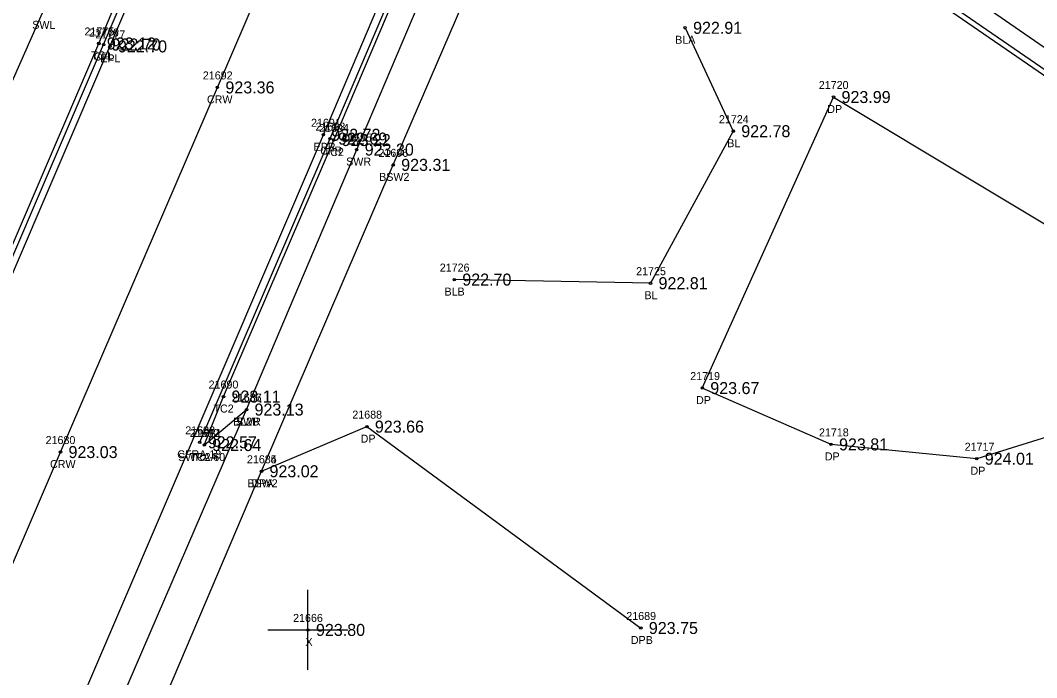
# Model space of a CAD drawing. Extents: x 1576181 to 1577685, y 1099396 to 1101490.
# Drawn here: x 1577167.3 to 1577294.3, y 1100920.8 to 1101003 of the extents above; entities that cross this region are included whole.
import ezdxf

# ---------------------------------------------------------------- set-up
doc = ezdxf.new("R2010")
doc.units = 0
for name, color, linetype in [('RD_DTM_BkLn1', 7, 'Continuous'), ('RD_DTM_BkLn2', 7, 'Continuous'), ('RD_DTM_BkLn_txCode', 7, 'Continuous'), ('RD_EX_Conc', 7, 'Continuous'), ('RD_EX_Conc_txCode', 7, 'Continuous'), ('RD_EX_Driveway', 7, 'Continuous'), ('RD_EX_Driveway_txCode', 7, 'Continuous'), ('RD_EX_Misc', 7, 'Continuous'), ('RD_EX_Misc_txCode', 7, 'Continuous'), ('RD_EX_Road', 7, 'Continuous'), ('RD_EX_Road_txCode', 7, 'Continuous'), ('RD_EX_TX_Conc_ELEV', 7, 'Continuous'), ('RD_EX_TX_Driveway_ELEV', 7, 'Continuous'), ('RD_EX_TX_Misc_ELEV', 7, 'Continuous'), ('RD_EX_TX_Road_ELEV', 7, 'Continuous'), ('RD_HC_Survey_ELEV', 7, 'Continuous'), ('RD_HC_Survey_txCode', 7, 'Continuous'), ('RD_SMD_Locator', 7, 'Continuous')]:
    doc.layers.add(name, color=color, linetype=linetype)

msp = doc.modelspace()

# ---------------------------------------------------------------- linework, layer by layer
at = {"layer": 'RD_DTM_BkLn1'}
msp.add_line((1577174.89, 1100906.42), (1577195.57, 1100954.33), dxfattribs=at)
for points in [[(1576908.25, 1100441.74), (1576920.44, 1100463.64), (1576944.47, 1100507.42), (1576973.89, 1100560.12), (1576993.13, 1100594.33), (1577014.77, 1100632.79), (1577042.14, 1100681.68), (1577066.82, 1100725.12), (1577089.75, 1100766.04), (1577111.87, 1100810.02), (1577132.74, 1100857.48), (1577152.58, 1100903.02), (1577172.32, 1100949.02), (1577191.93, 1100994.6), (1577211.77, 1101040.76), (1577222.24, 1101065.99), (1577231.17, 1101086.4), (1577251.41, 1101132.37), (1577271.56, 1101178.18), (1577291.61, 1101224.24), (1577311.77, 1101270.05), (1577333.79, 1101320.46), (1577355.93, 1101371.29), (1577365.01, 1101392.03)], [(1577250.38, 1101002.05), (1577256.4, 1100989.13), (1577246.06, 1100970.13), (1577221.54, 1100970.58)]]:
    msp.add_lwpolyline(points, dxfattribs=at)
at = {"layer": 'RD_DTM_BkLn2'}
for points in [[(1577190.28, 1100949.9), (1577192.69, 1100955.96), (1577206.46, 1100988.02), (1577223.59, 1101028.27), (1577225.54, 1101030.74), (1577227.54, 1101032.05), (1577227.96, 1101031.82), (1577225.99, 1101027.04)], [(1577107.29, 1100837.15), (1577118.47, 1100863.11), (1577138.23, 1100909.32), (1577157.86, 1100955.31), (1577177.11, 1101000.09), (1577190, 1101030.75)], [(1577246.74, 1101029.36), (1577254.79, 1101023.97), (1577296.49, 1100995.27), (1577317.47, 1100980.16)]]:
    msp.add_lwpolyline(points, dxfattribs=at)
at = {"layer": 'RD_EX_Conc'}
for points in [[(1577079.25, 1100805.08), (1577097.11, 1100838.84), (1577109.69, 1100867.34), (1577130.74, 1100915.04), (1577150.18, 1100959), (1577170.08, 1101003.92), (1577196.78, 1101064.66), (1577202.49, 1101060)], [(1577189.73, 1100950.24), (1577206.01, 1100988.2), (1577223.14, 1101028.48), (1577225.21, 1101031.19), (1577227.4, 1101032.52), (1577228.46, 1101031.9), (1577226.35, 1101026.9)], [(1577107.98, 1100836.94), (1577119.09, 1100862.85), (1577138.71, 1100909.15), (1577158.46, 1100955.15), (1577177.7, 1100999.96), (1577190.71, 1101030.46)], [(1577247, 1101029.77), (1577255.15, 1101024.5), (1577296.85, 1100995.79), (1577317.96, 1100980.41)], [(1577190.28, 1100949.9), (1577195.57, 1100954.33), (1577209.34, 1100986.83), (1577226.35, 1101026.9)], [(1577055.15, 1100662.64), (1577085.17, 1100716.01), (1577085.17, 1100716.01), (1577107.37, 1100755.87), (1577118.9, 1100776.66), (1577132.78, 1100800.81), (1577154.83, 1100846.62), (1577163.04, 1100865.24), (1577174.66, 1100893.05), (1577197.44, 1100946.62), (1577213.9, 1100984.92), (1577231.04, 1101024.71)]]:
    msp.add_lwpolyline(points, dxfattribs=at)
at = {"layer": 'RD_EX_Driveway'}
for points in [[(1577332.84, 1100969.65), (1577326.58, 1100968.01), (1577315.89, 1100957.23), (1577286.83, 1100948.19), (1577268.62, 1100949.98), (1577252.53, 1100957.02), (1577268.93, 1100993.4), (1577305.23, 1100971.57), (1577315.9, 1100975.76), (1577317.96, 1100980.41), (1577332.84, 1100969.65)], [(1577197.44, 1100946.62), (1577210.61, 1100952.2), (1577244.85, 1100927.03)]]:
    msp.add_lwpolyline(points, dxfattribs=at)
at = {"layer": 'RD_EX_Misc'}
for p, q in [((1577203.25, 1100921.79), (1577203.25, 1100931.79)), ((1577198.25, 1100926.79), (1577208.25, 1100926.79))]:
    msp.add_line(p, q, dxfattribs=at)
at = {"layer": 'RD_EX_Road'}
for points in [[(1577060.61, 1100805.43), (1577075.53, 1100798.54), (1577081.93, 1100797.67), (1577087.92, 1100798.37), (1577091.21, 1100799.4), (1577094.49, 1100804.27), (1577106.9, 1100832.16), (1577119.9, 1100862.62), (1577139.86, 1100909.4), (1577159.21, 1100954.77), (1577178.5, 1100999.73), (1577192.43, 1101032.31), (1577206.43, 1101064.72)], [(1577078.76, 1100718.33), (1577101.64, 1100758.92), (1577113.34, 1100780.09), (1577125.29, 1100804.69), (1577146.47, 1100851.25), (1577166.06, 1100897.32), (1577205.17, 1100988.68), (1577222.29, 1101028.96), (1577224.55, 1101032.02), (1577228.3, 1101034.47), (1577233.18, 1101036.1), (1577233.18, 1101036.1), (1577237.42, 1101035.84), (1577245.43, 1101032.85), (1577248.28, 1101031.55), (1577256.85, 1101026.16), (1577298.2, 1100997.6), (1577319.21, 1100982.29), (1577334.07, 1100971.38), (1577345.18, 1100963.67), (1577378, 1100938.95), (1577407.15, 1100918.71), (1577419.5, 1100910.06), (1577460.72, 1100880.37)]]:
    msp.add_lwpolyline(points, dxfattribs=at)
at = {"layer": 'RD_SMD_Locator'}
for centre in [(1577250.38, 1101002.05), (1577177.11, 1101000.09), (1577177.7, 1100999.96), (1577178.5, 1100999.73), (1577191.93, 1100994.6), (1577268.93, 1100993.4), (1577256.4, 1100989.13), (1577205.17, 1100988.68), (1577206.01, 1100988.2), (1577206.46, 1100988.02), (1577209.34, 1100986.83), (1577213.9, 1100984.92), (1577221.54, 1100970.58), (1577246.06, 1100970.13), (1577252.53, 1100957.02), (1577192.69, 1100955.96), (1577195.57, 1100954.33), (1577195.57, 1100954.33), (1577210.61, 1100952.2), (1577189.73, 1100950.24), (1577190.28, 1100949.9), (1577190.28, 1100949.9), (1577268.62, 1100949.98), (1577172.32, 1100949.02), (1577286.83, 1100948.19), (1577197.44, 1100946.62), (1577197.44, 1100946.62), (1577203.25, 1100926.79), (1577244.85, 1100927.03)]:
    msp.add_circle(centre, 0.15, dxfattribs=at)

# ---------------------------------------------------------------- texts
at = {"layer": 'RD_DTM_BkLn_txCode'}
for s, p in [('BLA', (1577249.14, 1101000.05)), ('21724', (1577254.61, 1100990.13)), ('BL', (1577255.65, 1100987.13)), ('21726', (1577219.72, 1100971.58)), ('21725', (1577244.26, 1100971.13)), ('BLB', (1577220.31, 1100968.58)), ('BL', (1577245.3, 1100968.13)), ('21687', (1577193.75, 1100955.33)), ('BL2B', (1577193.89, 1100952.33))]:
    msp.add_text(s, height=1, dxfattribs=at).set_placement(p)
at = {"layer": 'RD_EX_Conc_txCode'}
for s, p in [('SWL', (1577168.79, 1101001.92)), ('21775', (1577175.32, 1101001.09)), ('21776', (1577175.88, 1101000.96)), ('TC1', (1577176.15, 1100998.09)), ('CFL', (1577176.49, 1100997.96)), ('21693', (1577204.19, 1100989.2)), ('21694', (1577204.64, 1100989.02)), ('21695', (1577207.52, 1100987.83)), ('CFR', (1577204.78, 1100986.2)), ('TC2', (1577205.21, 1100986.02)), ('21696', (1577212.06, 1100985.92)), ('SWR', (1577208.02, 1100984.83)), ('BSW2', (1577212.14, 1100982.92)), ('21690', (1577190.83, 1100956.96)), ('21686', (1577193.72, 1100955.33)), ('TC2', (1577191.44, 1100953.96)), ('21683', (1577187.91, 1100951.24)), ('SWR', (1577194.25, 1100952.33)), ('21682', (1577188.46, 1100950.9)), ('21681', (1577188.74, 1100950.9)), ('CFRA 18', (1577186.91, 1100948.24)), ('SWRA 60', (1577187.03, 1100947.9)), ('TC2A', (1577188.55, 1100947.9)), ('21684', (1577195.62, 1100947.62)), ('BSW2', (1577195.67, 1100944.62))]:
    msp.add_text(s, height=1, dxfattribs=at).set_placement(p)
at = {"layer": 'RD_EX_Driveway_txCode'}
for s, p in [('21720', (1577267.09, 1100994.4)), ('DP', (1577268.15, 1100991.4)), ('21719', (1577251.02, 1100958.02)), ('DP', (1577251.75, 1100955.02)), ('21688', (1577208.79, 1100953.2)), ('DP', (1577209.83, 1100950.2)), ('21718', (1577267.11, 1100950.98)), ('21717', (1577285.32, 1100949.19)), ('21685', (1577195.62, 1100947.62)), ('DP', (1577267.84, 1100947.98)), ('DP', (1577286.05, 1100946.19)), ('DPA', (1577196.17, 1100944.62)), ('21689', (1577243.03, 1100928.03)), ('DPB', (1577243.6, 1100925.03))]:
    msp.add_text(s, height=1, dxfattribs=at).set_placement(p)
at = {"layer": 'RD_EX_Misc_txCode'}
for s, p in [('21666', (1577201.39, 1100927.79)), ('X', (1577202.94, 1100924.79))]:
    msp.add_text(s, height=1, dxfattribs=at).set_placement(p)
at = {"layer": 'RD_EX_Road_txCode'}
for s, p in [('21777', (1577176.7, 1101000.73)), ('EPL', (1577177.29, 1100997.73)), ('21691', (1577203.63, 1100989.68)), ('EPR', (1577203.94, 1100986.68))]:
    msp.add_text(s, height=1, dxfattribs=at).set_placement(p)
at = {"layer": 'RD_EX_TX_Conc_ELEV'}
for s, p in [('923.12', (1577178.11, 1100999.34)), ('922.70', (1577178.7, 1100999.21)), ('922.69', (1577207.01, 1100987.45)), ('923.22', (1577207.46, 1100987.27)), ('923.30', (1577210.34, 1100986.08)), ('923.31', (1577214.9, 1100984.17)), ('923.11', (1577193.69, 1100955.21)), ('923.13', (1577196.57, 1100953.58)), ('922.57', (1577190.73, 1100949.49)), ('922.64', (1577191.28, 1100949.15)), ('922.64', (1577191.28, 1100949.15)), ('923.02', (1577198.44, 1100945.87))]:
    msp.add_text(s, height=1.5, dxfattribs=at).set_placement(p)
at = {"layer": 'RD_EX_TX_Driveway_ELEV'}
for s, p in [('923.99', (1577269.93, 1100992.65)), ('923.67', (1577253.53, 1100956.27)), ('923.66', (1577211.61, 1100951.45)), ('923.81', (1577269.62, 1100949.23)), ('924.01', (1577287.83, 1100947.44)), ('923.02', (1577198.44, 1100945.87)), ('923.75', (1577245.85, 1100926.28))]:
    msp.add_text(s, height=1.5, dxfattribs=at).set_placement(p)
at = {"layer": 'RD_EX_TX_Misc_ELEV'}
for s, p in [('922.91', (1577251.38, 1101001.3)), ('922.78', (1577257.4, 1100988.38)), ('922.70', (1577222.54, 1100969.83)), ('922.81', (1577247.06, 1100969.38)), ('923.13', (1577196.57, 1100953.58)), ('923.80', (1577204.25, 1100926.04))]:
    msp.add_text(s, height=1.5, dxfattribs=at).set_placement(p)
at = {"layer": 'RD_EX_TX_Road_ELEV'}
for s, p in [('922.70', (1577179.5, 1100998.98)), ('922.72', (1577206.17, 1100987.93))]:
    msp.add_text(s, height=1.5, dxfattribs=at).set_placement(p)
at = {"layer": 'RD_HC_Survey_ELEV'}
for s, p in [('923.36', (1577192.93, 1100993.85)), ('923.03', (1577173.32, 1100948.27))]:
    msp.add_text(s, height=1.5, dxfattribs=at).set_placement(p)
at = {"layer": 'RD_HC_Survey_txCode'}
for s, p in [('21692', (1577190.11, 1100995.6)), ('CRW', (1577190.62, 1100992.6)), ('21680', (1577170.46, 1100950.02)), ('CRW', (1577171.01, 1100947.02))]:
    msp.add_text(s, height=1, dxfattribs=at).set_placement(p)

doc.saveas('drawing.dxf')
